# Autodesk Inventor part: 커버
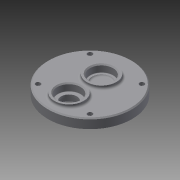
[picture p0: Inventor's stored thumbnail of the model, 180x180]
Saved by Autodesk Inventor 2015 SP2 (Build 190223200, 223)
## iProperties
Created: 2015-06
Part Number: 커버
Material: 일반
Document SubType Name: Modeling
Designer: AMC
Density: 1 g/cm^3
Appearance: 기본값
Author: AMC
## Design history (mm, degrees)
sketch "스케치1"
  geometry: C1 r 40 at (0, 0); 1 further point
  constraints: 1 centre point, 1 coincident
  dimensions: "d0" = 80 diameter of C1
extrude "돌출1" new body sketch "스케치1" distance "d1" = 9; taper "d2" = 0 deg
sketch "스케치2"
  geometry: C1 r 14 at (0, -20); C2 r 14 at (0, 11); 1 further point
  constraints: 2 centre point, 2 vertical alignment
  dimensions: "d3" = 11 distance of point (0, 0) C2.centre; "d4" = 20 distance of C1.centre point (0, 0); "d5" = 28 diameter of C1; "d6" = 28 diameter of C2
extrude "돌출2" join sketch "스케치2" distance "d7" = 3; taper "d8" = 0 deg
fillet "모깎기1" dims "d9" = 2
sketch "스케치3"
  geometry: C1 r 14 at (0, 0) reference; C2 r 14 at (0, -31) reference; C3 r 11 at (0, 0); C4 r 11 at (0, -31); 1 further point
  constraints: 2 centre point, 2 coincident
  dimensions: "d10" = 22 diameter of C3; "d11" = 22 diameter of C4
extrude "돌출3" cut sketch "스케치3" distance "d12" = 7; taper "d13" = 0 deg
sketch "스케치4"
  geometry: C1 r 11 at (0, -31) reference; C2 r 40 at (0, -11) reference; C3 r 9 at (0, 0); 2 further points
  constraints: 1 centre point, 1 coincident, 1 vertical alignment
  dimensions: "d14" = 18 diameter of C3
extrude "돌출4" cut sketch "스케치4" distance "d15" = 1; taper "d16" = 0 deg
fillet "모깎기2" dims "d17" = 2
fillet "모깎기3" dims "d18" = 0.3
chamfer "모따기1" distance "d19" = 1; stored, may be unused: second distance "d20" = 2, angle "d21" = 45 deg
sketch "스케치5"
  geometry: C1 r 10.7 at (0, 0) reference; C2 r 10.7 at (0, 31) reference; C3 r 9 at (0, 31) reference; C4 r 40 at (0, 20) reference; C5 r 7.5 at (0, 0); 1 further point
  constraints: 1 centre point, 1 coincident
  dimensions: "d22" = 15 diameter of C5
extrude "돌출5" cut sketch "스케치5" distance "d23" = 2; taper "d24" = 0 deg
sketch "스케치6"
  geometry: C1 r 7.5 at (0, -20) reference; C2 r 11 at (0, -20); 1 further point
  constraints: 1 centre point, 1 coincident
  dimensions: "d25" = 22 diameter of C2
extrude "돌출6" cut sketch "스케치6" distance "d26" = 3; taper "d27" = 0 deg
sketch "스케치7"
  geometry: C1 r 11 at (0, -20) reference; C2 r 40 at (0, 0) reference; C3 r 15 at (0, -20); 1 further point
  constraints: 1 centre point, 1 coincident
  dimensions: "d28" = 30 diameter of C3
extrude "돌출7" join sketch "스케치7" distance "d29" = 4; taper "d30" = 0 deg
chamfer "모따기2" distance "d31" = 1; stored, may be unused: second distance "d32" = 2, angle "d33" = 45 deg
fillet "모깎기4" dims "d34" = 0.3
chamfer "모따기3" distance "d35" = 1; stored, may be unused: second distance "d36" = 2, angle "d37" = 45 deg
fillet "모깎기5" dims "d38" = 2
sketch "스케치8"
  geometry: L1 (0, 0)-(0, 35); L2 (0, 0)-(-24.749, 24.749)
  constraints: 4 end point, 1 vertical
  dimensions: "d39" = 35 distance of L1.start L1.end; "d40" = 35 distance of L1.start L2.end; "d41" = 45 deg angle of L1 L2
hole "구멍1" sketch "스케치8" at (-24.749, 24.749) diameter "d42" = 4.5; stored, may be unused: countersink angle "d46" = 90 deg, drill point angle "d48" = 118 deg; dims "d43" = 6, "d44" = 8, "d45" = 4.4, "d47" = 8
node "솔리드1"
pattern_circular "원형 패턴1" dims angle "d50" = 360 deg
node "투영된 루프1"
node "절단 모서리 투영1"
node "절단 모서리 투영2"
node "절단 모서리 투영3"
node "절단 모서리 투영4"
